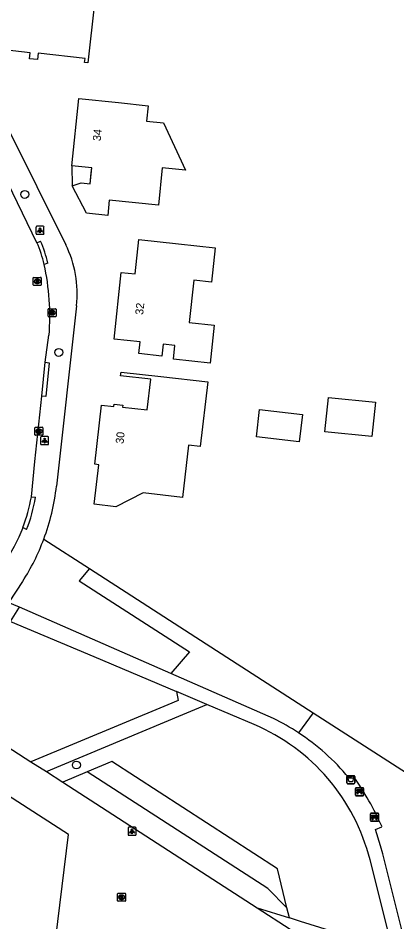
# Model space of a CAD drawing. Extents: x 162398 to 163643, y 386453 to 387397.
# Drawn here: x 163175 to 163222.4, y 386571.3 to 386684.2 of the extents above; entities that cross this region are included whole.
import ezdxf

# ---------------------------------------------------------------- set-up
doc = ezdxf.new("R2010")
doc.units = 0
for name, color, linetype in [('IMGEO_Afvalbak', 7, 'Continuous'), ('IMGEO_Bank', 7, 'Continuous'), ('IMGEO_Boom', 7, 'Continuous'), ('IMGEO_Groenvoorziening', 7, 'Continuous'), ('IMGEO_Kolk', 7, 'Continuous'), ('IMGEO_Lichtpunt', 7, 'Continuous'), ('IMGEO_Pand', 7, 'Continuous'), ('IMGEO_Pand_nummerreeks', 7, 'Continuous'), ('IMGEO_Pand_overbouw', 7, 'Continuous'), ('IMGEO_Rijbaan_lokaal_open', 7, 'Continuous'), ('IMGEO_Rioolput', 7, 'Continuous'), ('IMGEO_Voetpad_halfverhard', 7, 'Continuous'), ('IMGEO_Voetpad_open', 7, 'Continuous')]:
    doc.layers.add(name, color=color, linetype=linetype)

msp = doc.modelspace()

# ---------------------------------------------------------------- linework, layer by layer
at = {"layer": 'IMGEO_Afvalbak'}
for p, q in [((163216.15, 386588.67), (163216.15, 386589.47)), ((163216.15, 386589.47), (163216.15, 386588.67)), ((163216.25, 386589.57), (163217.04, 386589.57)), ((163217.04, 386589.57), (163216.25, 386589.57)), ((163217.14, 386589.47), (163217.14, 386588.67)), ((163217.14, 386588.67), (163217.14, 386589.47)), ((163217.04, 386588.57), (163216.25, 386588.57)), ((163216.25, 386588.57), (163217.04, 386588.57))]:
    msp.add_line(p, q, dxfattribs=at)
msp.add_lwpolyline([(163216.29, 386589.29), (163217, 386589.29), (163216.85, 386588.82), (163216.44, 386588.82), (163216.29, 386589.29)], dxfattribs=at)
for centre, start, end in [((163216.25, 386589.47), 90, 180), ((163216.25, 386589.47), 90, 180), ((163217.04, 386589.47), 0, 90), ((163217.04, 386589.47), 360, 90), ((163216.25, 386588.67), 180, 270), ((163216.25, 386588.67), 180, 270), ((163217.04, 386588.67), 270, 0), ((163217.04, 386588.67), 270, 0)]:
    msp.add_arc(centre, 0.1, start, end, dxfattribs=at)
at = {"layer": 'IMGEO_Bank'}
for p, q in [((163217.25, 386587.13), (163217.25, 386587.97)), ((163217.25, 386587.97), (163217.25, 386587.13)), ((163217.32, 386588.06), (163218.16, 386588.06)), ((163218.16, 386588.06), (163217.32, 386588.06)), ((163218.25, 386587.98), (163218.25, 386587.14)), ((163218.25, 386587.14), (163218.25, 386587.98)), ((163218.17, 386587.06), (163217.33, 386587.06)), ((163217.33, 386587.06), (163218.17, 386587.06)), ((163217.94, 386587.46), (163217.55, 386587.46)), ((163217.56, 386587.56), (163217.56, 386587.67)), ((163217.6, 386587.67), (163217.6, 386587.56)), ((163217.89, 386587.68), (163217.61, 386587.68)), ((163217.61, 386587.56), (163217.89, 386587.56)), ((163217.89, 386587.56), (163217.89, 386587.67)), ((163217.94, 386587.67), (163217.94, 386587.56)), ((163219.13, 386583.95), (163219.13, 386584.79)), ((163219.13, 386584.79), (163219.13, 386583.95)), ((163219.2, 386584.87), (163220.04, 386584.87)), ((163220.04, 386584.87), (163219.2, 386584.87)), ((163219.44, 386584.38), (163219.44, 386584.49)), ((163219.48, 386584.49), (163219.48, 386584.38)), ((163219.77, 386584.49), (163219.49, 386584.49)), ((163219.49, 386584.37), (163219.77, 386584.37)), ((163219.77, 386584.38), (163219.77, 386584.49)), ((163219.82, 386584.49), (163219.82, 386584.38)), ((163220.13, 386584.8), (163220.13, 386583.96)), ((163220.13, 386583.96), (163220.13, 386584.8)), ((163220.05, 386583.87), (163219.21, 386583.87)), ((163219.21, 386583.87), (163220.05, 386583.87)), ((163219.82, 386584.27), (163219.43, 386584.27))]:
    msp.add_line(p, q, dxfattribs=at)
for points in [[(163217.55, 386587.68), (163217.46, 386587.68), (163217.46, 386587.84), (163218.03, 386587.84), (163218.03, 386587.68), (163217.94, 386587.68)], [(163217.49, 386587.46), (163217.35, 386587.46), (163217.46, 386587.56), (163217.55, 386587.56)], [(163217.54, 386587.45), (163217.54, 386587.24), (163217.5, 386587.24), (163217.5, 386587.45)], [(163217.94, 386587.56), (163218.03, 386587.56), (163218.14, 386587.46), (163218, 386587.46)], [(163217.99, 386587.45), (163217.99, 386587.24), (163217.95, 386587.24), (163217.95, 386587.45)], [(163219.37, 386584.27), (163219.23, 386584.27), (163219.34, 386584.37), (163219.43, 386584.37)], [(163219.43, 386584.49), (163219.34, 386584.49), (163219.34, 386584.65), (163219.91, 386584.65), (163219.91, 386584.49), (163219.82, 386584.49)], [(163219.82, 386584.37), (163219.91, 386584.37), (163220.02, 386584.27), (163219.88, 386584.27)], [(163219.42, 386584.27), (163219.42, 386584.06), (163219.38, 386584.06), (163219.38, 386584.27)], [(163219.87, 386584.27), (163219.87, 386584.06), (163219.83, 386584.06), (163219.83, 386584.27)]]:
    msp.add_lwpolyline(points, dxfattribs=at)
for centre, radius, start, end in [((163217.32, 386587.98), 0.0779, 92.4484, 184.2845), ((163217.32, 386587.98), 0.0779, 92.4484, 184.2845), ((163218.17, 386587.98), 0.0779, 2.4484, 94.2845), ((163218.17, 386587.98), 0.0779, 2.4484, 94.2845), ((163217.32, 386587.14), 0.0779, 182.4484, 274.2845), ((163217.32, 386587.14), 0.0779, 182.4484, 274.2845), ((163217.49, 386587.45), 0.00671, 2.8957, 87.1043), ((163217.55, 386587.45), 0.00671, 92.8957, 177.1043), ((163217.55, 386587.67), 0.00671, 2.8957, 87.1043), ((163217.55, 386587.56), 0.00671, 272.8957, 357.1043), ((163217.61, 386587.67), 0.00671, 92.8957, 177.1043), ((163217.61, 386587.56), 0.00671, 182.8957, 267.1043), ((163217.89, 386587.67), 0.00671, 2.8957, 87.1043), ((163217.89, 386587.56), 0.00671, 272.8957, 357.1043), ((163217.94, 386587.67), 0.00671, 92.8957, 177.1043), ((163217.94, 386587.56), 0.00671, 182.8957, 267.1043), ((163217.94, 386587.45), 0.00671, 2.8957, 87.1043), ((163218, 386587.45), 0.00671, 92.8957, 177.1043), ((163218.17, 386587.14), 0.0779, 272.4484, 4.2845), ((163218.17, 386587.14), 0.0779, 272.4484, 4.2845), ((163219.2, 386584.8), 0.0779, 92.4484, 184.2845), ((163219.2, 386584.8), 0.0779, 92.4484, 184.2845), ((163219.43, 386584.49), 0.00671, 2.8957, 87.1043), ((163219.43, 386584.38), 0.00671, 272.8957, 357.1043), ((163219.49, 386584.49), 0.00671, 92.8957, 177.1043), ((163219.49, 386584.38), 0.00671, 182.8957, 267.1043), ((163219.77, 386584.49), 0.00671, 2.8957, 87.1043), ((163219.77, 386584.38), 0.00671, 272.8957, 357.1043), ((163219.82, 386584.49), 0.00671, 92.8957, 177.1043), ((163219.82, 386584.38), 0.00671, 182.8957, 267.1043), ((163220.05, 386584.8), 0.0779, 2.4484, 94.2845), ((163220.05, 386584.8), 0.0779, 2.4484, 94.2845), ((163219.2, 386583.95), 0.0779, 182.4484, 274.2845), ((163219.2, 386583.95), 0.0779, 182.4484, 274.2845), ((163219.37, 386584.26), 0.00671, 2.8957, 87.1043), ((163219.43, 386584.26), 0.00671, 92.8957, 177.1043), ((163219.82, 386584.26), 0.00671, 2.8957, 87.1043), ((163219.88, 386584.26), 0.00671, 92.8957, 177.1043), ((163220.05, 386583.95), 0.0779, 272.4484, 4.2845), ((163220.05, 386583.95), 0.0779, 272.4484, 4.2845)]:
    msp.add_arc(centre, radius, start, end, dxfattribs=at)
at = {"layer": 'IMGEO_Boom'}
for centre in [(163175.86, 386662.19), (163180.11, 386642.45), (163182.32, 386590.9)]:
    msp.add_circle(centre, 0.489, dxfattribs=at)
at = {"layer": 'IMGEO_Groenvoorziening'}
for points in [[(163178.24, 386619.12), (163183.96, 386615.44)], [(163183.96, 386615.44), (163182.67, 386613.9), (163196.46, 386605.03), (163194.14, 386602.32)], [(163183.96, 386615.44), (163198.56, 386606.06), (163211.96, 386597.43)], [(163211.96, 386597.43), (163210.09, 386594.93)], [(163211.96, 386597.43), (163249.43, 386573.34)], [(163208.66, 386573.07), (163207.49, 386577.94), (163186.76, 386591.35), (163183.68, 386590.07)], [(163183.68, 386590.07), (163180.6, 386588.78)], [(163208.66, 386573.07), (163206.26, 386575.46), (163183.68, 386590.07)], [(163208.96, 386571.8), (163208.66, 386573.07)]]:
    msp.add_lwpolyline(points, dxfattribs=at)
at = {"layer": 'IMGEO_Kolk'}
for p, q in [((163178.78, 386646.98), (163178.78, 386647.84)), ((163178.85, 386647.91), (163179.7, 386647.91)), ((163179.26, 386647.69), (163179.29, 386647.69)), ((163179.78, 386647.84), (163179.78, 386646.98)), ((163179.7, 386646.91), (163178.85, 386646.91)), ((163179.29, 386647.13), (163179.26, 386647.13)), ((163177.12, 386632.17), (163177.12, 386633.03)), ((163177.2, 386633.1), (163178.05, 386633.1)), ((163178.13, 386633.03), (163178.13, 386632.17)), ((163178.05, 386632.1), (163177.2, 386632.1)), ((163177.61, 386632.88), (163177.64, 386632.88)), ((163177.63, 386632.32), (163177.61, 386632.32)), ((163187.47, 386573.95), (163187.47, 386574.81)), ((163187.55, 386574.88), (163188.4, 386574.88)), ((163187.96, 386574.66), (163187.99, 386574.66)), ((163188.47, 386574.81), (163188.47, 386573.95)), ((163188.4, 386573.88), (163187.55, 386573.88)), ((163187.98, 386574.1), (163187.96, 386574.1))]:
    msp.add_line(p, q, dxfattribs=at)
for points in [[(163178.78, 386646.98), (163178.78, 386647.84)], [(163178.85, 386647.91), (163179.7, 386647.91)], [(163179.1, 386647.61), (163179.22, 386647.61), (163179.22, 386647.46), (163179.35, 386647.61), (163179.51, 386647.61), (163179.37, 386647.46), (163179.52, 386647.21), (163179.37, 386647.21), (163179.28, 386647.37), (163179.22, 386647.31), (163179.22, 386647.21), (163179.1, 386647.21), (163179.1, 386647.61)], [(163179.78, 386647.84), (163179.78, 386646.98)], [(163179.7, 386646.91), (163178.85, 386646.91)], [(163177.12, 386632.17), (163177.12, 386633.03)], [(163177.2, 386633.1), (163178.05, 386633.1)], [(163178.13, 386633.03), (163178.13, 386632.17)], [(163178.05, 386632.1), (163177.2, 386632.1)], [(163177.44, 386632.8), (163177.57, 386632.8), (163177.57, 386632.65), (163177.7, 386632.8), (163177.86, 386632.8), (163177.72, 386632.65), (163177.87, 386632.4), (163177.72, 386632.4), (163177.63, 386632.56), (163177.57, 386632.5), (163177.57, 386632.4), (163177.44, 386632.4), (163177.44, 386632.8)], [(163187.47, 386573.95), (163187.47, 386574.81)], [(163187.55, 386574.88), (163188.4, 386574.88)], [(163187.79, 386574.58), (163187.92, 386574.58), (163187.92, 386574.43), (163188.05, 386574.58), (163188.21, 386574.58), (163188.06, 386574.43), (163188.22, 386574.18), (163188.06, 386574.18), (163187.98, 386574.34), (163187.92, 386574.28), (163187.92, 386574.18), (163187.79, 386574.18), (163187.79, 386574.58)], [(163188.47, 386574.81), (163188.47, 386573.95)], [(163188.4, 386573.88), (163187.55, 386573.88)]]:
    msp.add_lwpolyline(points, dxfattribs=at)
for centre, start, end in [((163178.85, 386647.83), 91.552, 178.448), ((163178.85, 386647.83), 91.552, 178.448), ((163179.7, 386647.83), 1.552, 88.448), ((163179.7, 386647.83), 1.552, 88.448), ((163178.85, 386646.98), 181.552, 268.448), ((163178.85, 386646.98), 181.552, 268.448), ((163179.7, 386646.98), 271.552, 358.448), ((163179.7, 386646.98), 271.552, 358.448), ((163177.2, 386633.02), 91.552, 178.448), ((163177.2, 386633.02), 91.552, 178.448), ((163178.05, 386633.02), 1.552, 88.448), ((163178.05, 386633.02), 1.552, 88.448), ((163177.2, 386632.17), 181.552, 268.448), ((163177.2, 386632.17), 181.552, 268.448), ((163178.05, 386632.17), 271.552, 358.448), ((163178.05, 386632.17), 271.552, 358.448), ((163187.55, 386574.8), 91.552, 178.448), ((163187.55, 386574.8), 91.552, 178.448), ((163188.4, 386574.8), 1.552, 88.448), ((163188.4, 386574.8), 1.552, 88.448), ((163187.55, 386573.96), 181.552, 268.448), ((163187.55, 386573.96), 181.552, 268.448), ((163188.4, 386573.96), 271.552, 358.448), ((163188.4, 386573.96), 271.552, 358.448)]:
    msp.add_arc(centre, 0.0765, start, end, dxfattribs=at)
for centre, major_axis, ratio, start_param, end_param in [((163179.26, 386647.41), (-0.387, 0.002), 0.722429, 4.712389, 7.853982), ((163179.29, 386647.41), (-0.39, 0.002), 0.717154, 1.570796, 4.712389), ((163177.61, 386632.6), (-0.387, 0.002), 0.722429, 4.712389, 7.853982), ((163177.64, 386632.6), (-0.39, 0.002), 0.717154, 1.570796, 4.712389), ((163187.96, 386574.38), (-0.387, 0.002), 0.722429, 4.712389, 7.853982), ((163187.98, 386574.38), (-0.39, 0.002), 0.717154, 1.570796, 4.712389)]:
    msp.add_ellipse(centre, major_axis=major_axis, ratio=ratio, start_param=start_param, end_param=end_param, dxfattribs=at)
at = {"layer": 'IMGEO_Lichtpunt'}
for p, q in [((163177.26, 386658.12), (163177.26, 386657.31)), ((163177.26, 386658.12), (163177.26, 386657.31)), ((163178.17, 386658.21), (163177.36, 386658.21)), ((163178.17, 386658.21), (163177.36, 386658.21)), ((163178.26, 386657.31), (163178.26, 386658.12)), ((163178.26, 386657.31), (163178.26, 386658.12)), ((163177.36, 386657.22), (163178.17, 386657.22)), ((163177.36, 386657.22), (163178.17, 386657.22)), ((163177.84, 386631.84), (163177.84, 386631.03)), ((163177.84, 386631.84), (163177.84, 386631.03)), ((163178.74, 386631.94), (163177.93, 386631.94)), ((163178.74, 386631.94), (163177.93, 386631.94)), ((163178.84, 386631.03), (163178.84, 386631.84)), ((163178.84, 386631.03), (163178.84, 386631.84)), ((163177.93, 386630.94), (163178.74, 386630.94)), ((163177.93, 386630.94), (163178.74, 386630.94)), ((163188.78, 386583.02), (163188.78, 386582.22)), ((163188.78, 386583.02), (163188.78, 386582.22)), ((163189.68, 386583.12), (163188.88, 386583.12)), ((163189.68, 386583.12), (163188.88, 386583.12)), ((163188.88, 386582.12), (163189.68, 386582.12)), ((163188.88, 386582.12), (163189.68, 386582.12)), ((163189.78, 386582.22), (163189.78, 386583.02)), ((163189.78, 386582.22), (163189.78, 386583.02))]:
    msp.add_line(p, q, dxfattribs=at)
for points in [[(163177.64, 386657.78), (163177.68, 386657.75), (163177.49, 386657.49), (163177.45, 386657.52), (163177.64, 386657.78)], [(163177.85, 386657.75), (163177.89, 386657.78), (163178.08, 386657.52), (163178.04, 386657.49), (163177.85, 386657.75)], [(163177.74, 386657.73), (163177.79, 386657.73), (163177.79, 386657.41), (163177.74, 386657.41), (163177.74, 386657.73)], [(163178.21, 386631.5), (163178.25, 386631.48), (163178.06, 386631.21), (163178.03, 386631.24), (163178.21, 386631.5)], [(163178.31, 386631.46), (163178.36, 386631.46), (163178.36, 386631.13), (163178.31, 386631.13), (163178.31, 386631.46)], [(163178.42, 386631.48), (163178.46, 386631.5), (163178.65, 386631.24), (163178.61, 386631.21), (163178.42, 386631.48)], [(163189.16, 386582.69), (163189.2, 386582.66), (163189.01, 386582.4), (163188.97, 386582.43), (163189.16, 386582.69)], [(163189.26, 386582.64), (163189.31, 386582.64), (163189.31, 386582.32), (163189.26, 386582.32), (163189.26, 386582.64)], [(163189.37, 386582.66), (163189.41, 386582.69), (163189.59, 386582.42), (163189.56, 386582.4), (163189.37, 386582.66)]]:
    msp.add_lwpolyline(points, dxfattribs=at)
for centre in [(163177.76, 386657.92), (163178.34, 386631.64), (163189.28, 386582.82)]:
    msp.add_circle(centre, 0.0994, dxfattribs=at)
for centre, start, end in [((163177.36, 386658.12), 90, 180), ((163177.36, 386658.12), 90, 180), ((163178.17, 386658.12), 0, 90), ((163178.17, 386658.12), 0, 90), ((163177.36, 386657.31), 180, 270), ((163177.36, 386657.31), 180, 270), ((163178.17, 386657.31), 270, 0), ((163178.17, 386657.31), 270, 360), ((163177.93, 386631.84), 90, 180), ((163177.93, 386631.84), 90, 180), ((163178.74, 386631.84), 0, 90), ((163178.74, 386631.84), 0, 90), ((163177.93, 386631.03), 180, 270), ((163177.93, 386631.03), 180, 270), ((163178.74, 386631.03), 270, 0), ((163178.74, 386631.03), 270, 360), ((163188.88, 386583.02), 90, 180), ((163188.88, 386583.02), 90, 180), ((163188.88, 386582.22), 180, 270), ((163188.88, 386582.22), 180, 270), ((163189.68, 386583.02), 0, 90), ((163189.68, 386583.02), 0, 90), ((163189.68, 386582.22), 270, 0), ((163189.68, 386582.22), 270, 360)]:
    msp.add_arc(centre, 0.0946, start, end, dxfattribs=at)
at = {"layer": 'IMGEO_Pand'}
for points in [[(163181.54, 386686.45), (163184.59, 386686.1), (163183.74, 386678.63), (163183.34, 386678.67), (163183.4, 386679.17), (163177.54, 386679.84), (163177.44, 386679.04), (163176.44, 386679.15), (163176.52, 386679.88), (163173.26, 386680.25), (163173.86, 386685.52), (163174.08, 386687.46), (163170.91, 386687.82), (163170.7, 386685.91), (163170.36, 386685.95), (163171.09, 386692.36), (163176.05, 386691.79), (163182.07, 386691.11), (163181.54, 386686.45)], [(163187.58, 386673.67), (163191.3, 386673.28), (163191.09, 386671.35), (163193.22, 386671.12), (163195.95, 386665.23), (163193.05, 386665.53), (163192.57, 386660.84), (163186.43, 386661.48), (163186.23, 386659.56), (163183.59, 386659.84), (163181.78, 386663.28), (163182.91, 386663.64), (163184.03, 386663.52), (163184.18, 386664.88), (163184.24, 386665.51), (163181.73, 386665.77), (163182.61, 386674.19), (163187.58, 386673.67)], [(163187.93, 386652.45), (163189.66, 386652.27), (163190.11, 386656.55), (163195.09, 386656.02), (163199.68, 386655.53), (163199.22, 386651.24), (163197, 386651.48), (163196.43, 386646.17), (163199.55, 386645.84), (163199.04, 386641.12), (163194.47, 386641.61), (163194.65, 386643.33), (163193.18, 386643.49), (163193.02, 386641.99), (163190.12, 386642.3), (163190.28, 386643.77), (163187.04, 386644.11), (163187.93, 386652.45)], [(163192.87, 386639.43), (163198.74, 386638.77), (163197.82, 386630.7), (163196.35, 386630.87), (163195.61, 386624.34), (163190.68, 386624.9), (163187.24, 386623.17), (163184.56, 386623.48), (163185.12, 386628.42), (163184.61, 386628.48), (163185.45, 386635.88), (163187.02, 386635.7), (163187.06, 386636), (163188.12, 386635.88), (163188.09, 386635.62), (163191.18, 386635.27), (163191.62, 386639.1), (163187.85, 386639.53), (163187.9, 386640), (163192.87, 386639.43)], [(163213.42, 386632.54), (163213.85, 386636.82), (163219.72, 386636.24), (163219.3, 386631.96), (163213.42, 386632.54)], [(163210.59, 386634.71), (163210.2, 386631.29), (163204.83, 386631.9), (163205.22, 386635.32), (163210.59, 386634.71)]]:
    msp.add_lwpolyline(points, dxfattribs=at)
at = {"layer": 'IMGEO_Pand_overbouw'}
msp.add_lwpolyline([(163184.24, 386665.51), (163181.73, 386665.77), (163181.78, 386663.28), (163182.91, 386663.64), (163184.03, 386663.52)], close=True, dxfattribs=at)
at = {"layer": 'IMGEO_Rijbaan_lokaal_open'}
for points in [[(163177.37, 386656.16), (163170.68, 386669.85)], [(163178.42, 386641.23), (163178.88, 386644.6)], [(163177.99, 386637), (163178.42, 386641.23)], [(163176.69, 386624.41), (163177.1, 386628.84), (163177.99, 386637)]]:
    msp.add_lwpolyline(points, dxfattribs=at)
for centre, radius, start, end in [((163164.82, 386650.46), 13.79, 12.5083, 24.4374), ((163149.49, 386647.02), 29.5, 355.2787, 12.5703), ((163156.29, 386627.97), 20.7, 339.0773, 350.086), ((163156.24, 386628.01), 20.77, 324.851, 339.0421)]:
    msp.add_arc(centre, radius, start, end, dxfattribs=at)
at = {"layer": 'IMGEO_Rioolput'}
for p, q in [((163176.92, 386650.9), (163176.92, 386651.76)), ((163176.99, 386651.83), (163177.85, 386651.83)), ((163177.43, 386651.05), (163177.4, 386651.05)), ((163177.41, 386651.61), (163177.43, 386651.61)), ((163177.92, 386651.76), (163177.92, 386650.9)), ((163177.85, 386650.83), (163176.99, 386650.83))]:
    msp.add_line(p, q, dxfattribs=at)
for points in [[(163176.92, 386650.9), (163176.92, 386651.76)], [(163176.99, 386651.83), (163177.85, 386651.83)], [(163177.51, 386651.53), (163177.25, 386651.53), (163177.25, 386651.13)], [(163177.25, 386651.13), (163177.38, 386651.13), (163177.38, 386651.29), (163177.39, 386651.29)], [(163177.43, 386651.45), (163177.38, 386651.45), (163177.38, 386651.37)], [(163177.38, 386651.37), (163177.43, 386651.37)], [(163177.44, 386651.26), (163177.51, 386651.13), (163177.65, 386651.13), (163177.58, 386651.26)], [(163177.92, 386651.76), (163177.92, 386650.9)], [(163177.85, 386650.83), (163176.99, 386650.83)]]:
    msp.add_lwpolyline(points, dxfattribs=at)
for centre, radius, start, end in [((163176.99, 386651.76), 0.0765, 91.552, 178.448), ((163176.99, 386651.76), 0.0765, 91.552, 178.448), ((163177.39, 386651.24), 0.0533, 26.0293, 88.6989), ((163177.44, 386651.35), 0.0964, 77.0061, 93.1865), ((163177.42, 386651.56), 0.19, 274.7715, 282.9687), ((163177.45, 386651.41), 0.0378, 276.6634, 79.6772), ((163177.51, 386651.42), 0.109, 350.3612, 89.416), ((163177.5, 386651.42), 0.112, 277.5842, 350.9817), ((163177.49, 386651.2), 0.108, 29.5134, 73.7905), ((163177.84, 386651.76), 0.0765, 1.552, 88.448), ((163177.84, 386651.76), 0.0765, 1.552, 88.448), ((163176.99, 386650.91), 0.0765, 181.552, 268.448), ((163176.99, 386650.91), 0.0765, 181.552, 268.448), ((163177.84, 386650.91), 0.0765, 271.552, 358.448), ((163177.84, 386650.91), 0.0765, 271.552, 358.448)]:
    msp.add_arc(centre, radius, start, end, dxfattribs=at)
for centre, major_axis, ratio, start_param, end_param in [((163177.41, 386651.33), (-0.387, 0.002), 0.722429, 4.712389, 7.853982), ((163177.43, 386651.33), (-0.39, 0.002), 0.717154, 1.570796, 4.712389)]:
    msp.add_ellipse(centre, major_axis=major_axis, ratio=ratio, start_param=start_param, end_param=end_param, dxfattribs=at)
at = {"layer": 'IMGEO_Voetpad_halfverhard'}
for points in [[(163194.14, 386602.32), (163175.19, 386610.61)], [(163174.06, 386608.85), (163184.48, 386604.45), (163194.84, 386600.07)], [(163206.97, 386596.7), (163194.14, 386602.32)], [(163194.84, 386600.07), (163195.04, 386598.97), (163193.76, 386598.43), (163176.6, 386591.3)], [(163198.63, 386598.47), (163194.84, 386600.07)], [(163178.56, 386590.1), (163195.64, 386597.22), (163198.63, 386598.47)], [(163204.55, 386595.96), (163198.63, 386598.47)], [(163216.97, 386589.51), (163216.39, 386589.34)], [(163224.96, 386562.63), (163220.67, 386579.81), (163220.37, 386580.82), (163219.75, 386582.84), (163220.55, 386583.19)], [(163221.89, 386567.79), (163219.06, 386579.05)], [(163204.93, 386573.05), (163208.96, 386571.8)], [(163221.89, 386567.79), (163210.36, 386571.36), (163208.96, 386571.8)]]:
    msp.add_lwpolyline(points, dxfattribs=at)
for centre, radius, start, end in [((163194.81, 386572.94), 25, 14.1469, 67.0903), ((163194.31, 386570.76), 28.87, 56.8503, 63.973), ((163194.43, 386570.96), 28.63, 39.9277, 56.8402), ((163185.92, 386567.72), 37.93, 24.0594, 35.0488)]:
    msp.add_arc(centre, radius, start, end, dxfattribs=at)
at = {"layer": 'IMGEO_Voetpad_open'}
for points in [[(163147.94, 386722.82), (163159.24, 386699.58), (163180.98, 386655.91)], [(163177.37, 386656.16), (163177.84, 386656.34)], [(163178.74, 386653.62), (163178.28, 386653.44)], [(163182.34, 386648.27), (163179.82, 386625.74)], [(163178.42, 386641.23), (163178.91, 386641.17), (163178.48, 386636.94), (163177.99, 386637)], [(163176.69, 386624.41), (163177.18, 386624.35)], [(163176.08, 386620.32), (163175.63, 386620.58)], [(163175.19, 386610.61), (163174.47, 386610.93), (163173.89, 386611.18), (163173.94, 386611.27), (163175.6, 386613.85)], [(163174.06, 386608.85), (163175.12, 386610.51), (163175.19, 386610.61)], [(163165.43, 386598.49), (163176.6, 386591.3)], [(163208.29, 386563.8), (163179.46, 386566.95), (163181.34, 386582.22), (163162.87, 386594.07)], [(163176.6, 386591.3), (163178.56, 386590.1)], [(163178.56, 386590.1), (163180.6, 386588.78)], [(163180.6, 386588.78), (163204.93, 386573.05)], [(163204.93, 386573.05), (163209.05, 386570.41)]]:
    msp.add_lwpolyline(points, dxfattribs=at)
for centre, radius, start, end in [((163163.91, 386650.17), 15.23, 13.0763, 23.8695), ((163168.72, 386649.79), 13.7, 353.626, 26.5455), ((163152.21, 386628.84), 27.78, 339.5352, 353.5939), ((163158.67, 386627.24), 18.74, 338.325, 351.1359), ((163152.25, 386628.83), 27.74, 327.3197, 339.5241)]:
    msp.add_arc(centre, radius, start, end, dxfattribs=at)

# ---------------------------------------------------------------- texts
at = {"layer": 'IMGEO_Pand_nummerreeks'}
for s, rotation, p in [('34', 84.0586, (163185.35, 386668.82)), ('32', 83.8925, (163190.66, 386647.11)), ('30', 83.5221, (163188.2, 386630.99))]:
    msp.add_text(s, height=1, rotation=rotation, dxfattribs=at).set_placement(p)

doc.saveas('drawing.dxf')
